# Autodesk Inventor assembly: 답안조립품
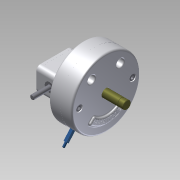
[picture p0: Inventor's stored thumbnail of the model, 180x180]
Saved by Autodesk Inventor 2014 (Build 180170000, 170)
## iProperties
Created: 2015-04
Part Number: 답안조립품
Document SubType Name: Assembly
Designer: Administrator
Mass: 1633.68 g
Surface Area: 3333.8 cm^2
Volume: 1140.86 cm^3
Density: 1.43197 g/cm^3
Author: Administrator
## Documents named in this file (15)
- C:\Documents and Settings\Administrator\바탕 화면\350406V1026\답안조립품.iam
- C:\Documents and Settings\Administrator\바탕 화면\350406V1026\본체.ipt
- C:\Documents and Settings\Administrator\바탕 화면\350406V1026\커버2.ipt
- C:\Documents and Settings\Administrator\바탕 화면\350406V1026\커버.ipt
- C:\Documents and Settings\Administrator\바탕 화면\350406V1026\베어링62_22.ipt
- C:\Documents and Settings\Administrator\바탕 화면\350406V1026\축.ipt
- C:\Documents and Settings\Administrator\바탕 화면\350406V1026\멈춤링.ipt
- C:\Documents and Settings\Administrator\바탕 화면\350406V1026\슬라이더3.ipt
- C:\Documents and Settings\Administrator\바탕 화면\350406V1026\가변스프링.ipt
- C:\Documents and Settings\Administrator\바탕 화면\350406V1026\부시.ipt
- C:\Documents and Settings\Administrator\바탕 화면\350406V1026\슬라이더2.ipt
- C:\Documents and Settings\Administrator\바탕 화면\350406V1026\슬라이더.ipt
- C:\Documents and Settings\Administrator\바탕 화면\350406V1026\평행핀.ipt
- C:\Documents and Settings\Administrator\바탕 화면\350406V1026\M 5 x 12.ipt
- C:\Documents and Settings\Administrator\바탕 화면\350406V1026\M 10 x 35.ipt
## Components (6 placed, 4 different names)
1. 가변스프링:1
2. KS B 1320 B B 5 x  20:1 — 플러쉬:2
3. M 5 x 12:1
4. M 10 x 35:1
5. M 5 x 12:2
6. M 10 x 35:2
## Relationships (1: Flush 1)
- 플러쉬:2 [Flush]: KS B 1320 B B 5 x  20:1
